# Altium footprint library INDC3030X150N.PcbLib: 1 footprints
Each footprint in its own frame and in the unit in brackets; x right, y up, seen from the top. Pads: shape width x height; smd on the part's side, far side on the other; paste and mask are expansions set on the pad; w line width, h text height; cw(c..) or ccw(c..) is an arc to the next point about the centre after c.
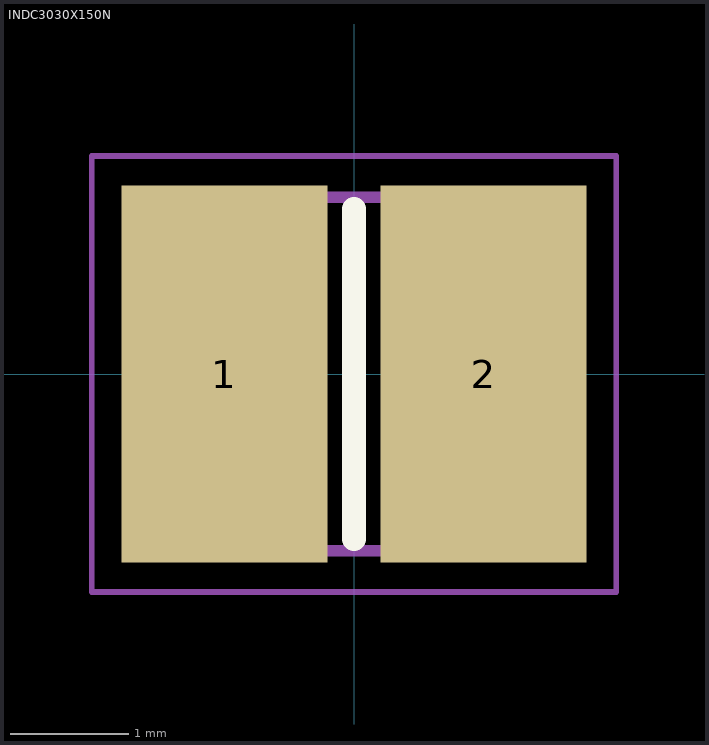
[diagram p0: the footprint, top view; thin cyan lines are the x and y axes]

## INDC3030X150N [mm]
pads (2):
  rect 1.75x3.2 smd: 1(-1.1,0) 2(1.1,0)
Top Overlay:
  lines w0.2: 0,-1.4 0,1.4
Mechanical 15:
  lines w0.1: -1.5,-1.5 1.5,-1.5 1.5,1.5 -1.5,1.5 -1.5,-1.5
Mechanical 20:
  lines w0.05: -2.225,-1.85 2.225,-1.85 2.225,1.85 -2.225,1.85 -2.225,-1.85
